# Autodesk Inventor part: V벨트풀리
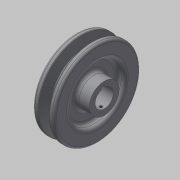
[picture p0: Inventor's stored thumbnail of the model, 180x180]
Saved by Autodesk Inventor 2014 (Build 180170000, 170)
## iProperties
Created: 2015-11
Part Number: V벨트풀리
Material: 강철, 탄소
Document SubType Name: Modeling
Designer: mduedu
Density: 1 g/cm^3
Appearance: 기본값
Author: mduedu
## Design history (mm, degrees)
sketch "스케치1"
  geometry: L1 (-9.5, 0)-(9.5, 0); L2 (0, 0)-(0, 37.7); L3 (-4.825, 37.7)-(-9.5, 37.7); L4 (-9.5, 37.7)-(-9.5, 0); L5 (0, 28.7)-(-2.074, 28.7); L6 (-2.074, 28.7)-(-4.825, 37.7); L7 (4.825, 37.7)-(9.5, 37.7); L8 (9.5, 37.7)-(9.5, 0); L9 (0, 28.7)-(2.074, 28.7); L10 (2.074, 28.7)-(4.825, 37.7); L11 (-9.5, 35)-(9.5, 35); 3 further points
  constraints: 22 end point, 7 point on line, 4 perpendicular, 3 symmetric about line, 1 coincident, 1 horizontal, 1 horizontal alignment, 1 midpoint, 1 vertical
  dimensions: "d0" = 19 distance of L1.start L1.end; "d2" = 75.4 diameter of L2.end L1 (derived); "d3" = 34 deg angle of L10 L6; "d4" = 6.3 distance between parallel lines of L11 L9; "d5" = 2.7 distance between parallel lines of L7 L11; "d6" = 8 distance of point (4, 35) point (-4, 35); "d7" = 70 diameter of L11 L1
revolve "회전1" sketch "스케치1" stored, may be unused: angle "d8" = 90 deg
sketch "스케치2"
  geometry: C1 r 24 at (0, 0); C2 r 13 at (0, 0); 1 further point
  constraints: 2 centre point, 2 coincident
  dimensions: "d9" = 48 diameter of C1; "d10" = 26 diameter of C2
extrude "돌출1" cut sketch "스케치2" distance "d11" = 6; taper "d12" = 0 deg
extrude "돌출3" join sketch "스케치2" distance "d37" = 6; taper "d38" = 0 deg
fillet "모깎기1" dims "d13" = 3
fillet "모깎기2" dims "d14" = 3
fillet "모깎기3" dims "d15" = 1, "d16" = 0.5, "d17" = 2
hole "구멍1" diameter "d20" = 16; stored, may be unused: countersink angle "d24" = 90 deg, drill point angle "d26" = 118 deg; dims "d21" = 6, "d22" = 4, "d23" = 2, "d25" = 8, "d53" = 10, "d54" = 10
sketch "스케치3"
  geometry: L1 (-2.5, 0)-(2.5, 0); L2 (2.5, 0)-(2.5, 10.3); L3 (2.5, 10.3)-(-2.5, 10.3); L4 (-2.5, 10.3)-(-2.5, 0); 2 further points
  constraints: 8 end point, 2 parallel, 1 coincident, 1 horizontal, 1 midpoint, 1 perpendicular
  dimensions: "d27" = 5 distance of L2.end L3.end; "d29" = 10.3 distance of L3.end L1.start
extrude "돌출2" cut sketch "스케치3" stored distance "d30" = 6; taper "d31" = 0 deg
chamfer "모따기1" distance "d32" = 1; stored, may be unused: second distance "d33" = 2, angle "d34" = 45 deg
node "작업 평면1"
sketch "스케치4"
  geometry: L1 (19, -27)-(19, 27) reference; 2 further points
  constraints: 1 horizontal alignment
  dimensions: "d52" = 22 distance from line of L1 point (-3, 0)
hole "구멍2" sketch "스케치4" at (-3, 0) diameter "d42" = 2.459; stored, may be unused: countersink angle "d46" = 90 deg, drill point angle "d48" = 118 deg; dims "d43" = 6, "d44" = 4, "d45" = 2, "d47" = 8
node "솔리드1"
mirror "대칭1"
